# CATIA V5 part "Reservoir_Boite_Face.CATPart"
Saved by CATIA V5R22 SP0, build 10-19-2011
Part number: Reservoir_Boite_Face
Bounding box of the stored display mesh (mm): x 0 to 5, y -94 to 94, z -47.5 to 47.5
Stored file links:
  D:\PER\CAO_PER_MODIF_2025\CAO_PER_pick&place_2024P\Sous_Ensemble_Boite\Reservoir_Boite\Reservoir_Boite_Face.CATPart
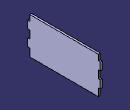
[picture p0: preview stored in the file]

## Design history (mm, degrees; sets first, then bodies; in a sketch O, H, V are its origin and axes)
Body1 (main body)
  Sketch1 on yz-plane, origin (0, 0, 0), H (0, 1, 0), V (0, 0, 1)
    line L1 (-94, 47.5) -> (94, 47.5)
    line L2 (94, 47.5) -> (94, -47.5)
    line L3 (94, -47.5) -> (-94, -47.5)
    line L4 (-94, -47.5) -> (-94, 47.5)
    length L1 = 188
    length L4 = 95
    horizontal: L1 H, L3 H
    vertical: L2 V, L4 V
    symmetry: L4 L2 V, L3 L1 H
  Pad1: profile Sketch1, direction (1, 0, 0), length 5
  Sketch2 on end face of Pad1, origin (5, 0, 0), H (0, 1, 0), V (0, 0, 1)
    point P1 (-94, -47.5)
    line L1 (-94, -47.5) -> (-89, -47.5)
    line L2 (-89, -47.5) -> (-89, -27.5)
    line L3 (-89, -27.5) -> (-94, -27.5)
    line L4 (-94, -27.5) -> (-94, -47.5)
    point P2 (-89, -47.5)
    point P3 (-89, -27.5)
    point P4 (-94, -27.5)
    reference projected point E1 (-94, -47.5) from vertex [face of Pad1 from Sketch1.L3 | end face of Pad1 | face of Pad1 from Sketch1.L4]
    point P5 (94, -47.5)
    point P6 (89, -47.5)
    point P7 (89, -27.5)
    point P8 (94, -27.5)
    line L5 (94, -47.5) -> (89, -47.5)
    line L6 (89, -47.5) -> (89, -27.5)
    line L7 (89, -27.5) -> (94, -27.5)
    line L8 (94, -27.5) -> (94, -47.5)
    length L4 = 20
    length L3 = 5
    horizontal: L1 H, L3 H
    vertical: L2 V, L4 V
    coincidence: P1 E1
    symmetry: P1 P5 V, P2 P6 V, P3 P7 V, P4 P8 V, L1 L5 V, L2 L6 V, L3 L7 V, L4 L8 V
  Pocket1: profile Sketch2, direction (-1, 0, 0), through (limit type 6)
  RectPattern1: of Pocket1, direction 1 instances 2, spacing 40, along edge [face of Pad1 from Sketch1.L4 | end face of Pad1] reversed
  Sketch3 on end face of Pad1, origin (5, 0, 0), H (0, 1, 0), V (0, 0, 1)
    point P1 (-94, 32.5)
    line L1 (-94, 32.5) -> (-89, 32.5)
    line L2 (-89, 32.5) -> (-89, 47.5)
    line L3 (-89, 47.5) -> (-94, 47.5)
    line L4 (-94, 47.5) -> (-94, 32.5)
    point P2 (-89, 32.5)
    point P3 (-89, 47.5)
    point P4 (-94, 47.5)
    reference projected point E1 (-94, 47.5) from vertex [face of Pad1 from Sketch1.L1 | end face of Pad1 | face of Pad1 from Sketch1.L4]
    reference projected line E2 (-89, 12.5) -> (-94, 12.5) from edge [end face of Pad1 | face of RectPattern1]
    reference projected line E3 (-89, -7.5) -> (-89, 12.5) from edge [end face of Pad1 | face of RectPattern1]
    point P5 (94, 32.5)
    point P6 (89, 32.5)
    point P7 (89, 47.5)
    point P8 (94, 47.5)
    line L5 (94, 32.5) -> (89, 32.5)
    line L6 (89, 32.5) -> (89, 47.5)
    line L7 (89, 47.5) -> (94, 47.5)
    line L8 (94, 47.5) -> (94, 32.5)
    distance L1 E2 = 20
    horizontal: L1 H, L3 H
    vertical: L2 V, L4 V
    coincidence: P4 E1, L2 E3
    symmetry: P1 P5 V, P2 P6 V, P3 P7 V, P4 P8 V, L1 L5 V, L2 L6 V, L3 L7 V, L4 L8 V
  Pocket2: profile Sketch3, direction (-1, 0, 0), through (limit type 6)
